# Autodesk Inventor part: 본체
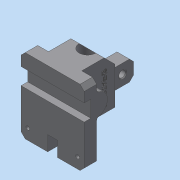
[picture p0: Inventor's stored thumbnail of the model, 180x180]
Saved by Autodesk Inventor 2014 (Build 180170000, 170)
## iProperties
Created: 2022-08
Part Number: 본체
Material: 일반
Document SubType Name: Modeling
Designer: dg
Density: 1 g/cm^3
Appearance: 기본값
Mass: 184.905 g
Surface Area: 337.564 cm^2
Volume: 184.905 cm^3
Author: dg
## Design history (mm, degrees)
sketch "스케치1"
  geometry: L1 (0, 0)-(27, 0); L2 (27, 0)-(45, -18); L3 (45, -18)-(45, -58); L4 (45, -58)-(4, -58); L5 (4, -58)-(4, -90); L6 (4, -90)-(0, -90); L7 (0, -90)-(0, 0)
  constraints: 14 end point, 4 parallel, 1 horizontal, 1 perpendicular
  dimensions: "d0" = 45 distance between parallel lines of L3 L7; "d1" = 18 horizontal distance of L1.end L2.end; "d2" = 45 deg angle of L2 L3; "d3" = 32 distance of L4.end L5.end; "d4" = 4 distance of L5.end L6.end; "d5" = 90 distance of L6.end L1.start
extrude "돌출1" new body sketch "스케치1" stored distance "d6" = 40; taper "d7" = 0 deg
sketch "스케치2"
  geometry: L1 (0, -90)-(0, 0) reference; L2 (0, 0)-(-15, 0); L3 (-15, 0)-(-15, -17); L4 (-15, -17)-(-7, -17); L5 (-7, -17)-(-7, -37); L6 (-7, -37)-(-15, -37); L7 (-15, -37)-(-15, -90); L8 (-15, -90)-(0, -90); A1 r 13 centre (0, -27) between (0, -40) and (0, -14); 1 further point
  constraints: 14 end point, 4 parallel, 3 point on line, 2 perpendicular, 2 point on circle, 1 centre point, 1 collinear, 1 horizontal alignment, 1 midpoint
  dimensions: "d8" = 13 radius of A1; "d9" = 20 distance of L4.end L5.end; "d10" = 27 distance from line of L2 A1.centre; "d11" = 8 distance of L3.end L4.end; "d12" = 8 distance of L5.end L6.end; "d13" = 15 distance of L1.end L2.end
extrude "돌출2" join sketch "스케치2" stored distance "d14" = 76; taper "d15" = 0 deg
sketch "스케치3"
  geometry: L1 (58, -60)-(-18, -60) reference; 3 further points
  constraints: 1 midpoint, 1 vertical alignment
  dimensions: "d16" = 42 distance from line of L1 point (20, -18)
hole "구멍1" sketch "스케치3" at (20, -18) diameter "d17" = 20; stored, may be unused: countersink angle "d21" = 90 deg, drill point angle "d23" = 118 deg; dims "d18" = 6, "d19" = 29, "d20" = 7, "d22" = 8
sketch "스케치4"
  geometry: L1 (0, 0)-(40, 0) reference; C1 r 10 at (20, 23) reference; A1 r 29 centre (20, 23) between (2.336, 0) and (37.664, 0); 1 further point
  constraints: 2 point on circle, 2 point on line, 1 centre point, 1 coincident
  dimensions: "d24" = 58 diameter of A1
extrude "돌출3" cut sketch "스케치4" distance "d25" = 18; taper "d26" = 0 deg
sketch "스케치5"
  geometry: L1 (76, 0)-(0, 0) reference; L2 (55.664, 19)-(58, 19) reference; L3 (32, 13.627)-(32, 0); L4 (44, 13.627)-(44, 0); A1 r 29 centre (38, 42) between (20.336, 19) and (55.664, 19) reference; 1 further point
  constraints: 4 end point, 2 perpendicular, 2 point on circle, 2 point on line, 1 horizontal alignment
  dimensions: "d27" = 12 distance between parallel lines of L3 L4
extrude "돌출4" cut sketch "스케치5" distance "d28" = 18; taper "d29" = 0 deg
sketch "스케치6"
  geometry: L1 (0, 50)-(18, 50) reference; L2 (-58, 50)-(-40, 50) reference; L3 (10, 37)-(-50, 37); L4 (-10, -40)-(-30, -40) reference; 3 further points
  constraints: 2 end point, 2 midpoint, 1 vertical alignment
  dimensions: "d30" = 13 distance from line of L2 L3.end; "d31" = 13 distance from line of L1 L3.start; "d32" = 60 distance of L3.end L3.start
hole "구멍2" sketch "스케치6" at (10, 37), (-50, 37) diameter "d33" = 4.5; stored, may be unused: countersink angle "d37" = 90 deg, drill point angle "d39" = 118 deg; dims "d34" = 6, "d35" = 8, "d36" = 4.4, "d38" = 8
sketch "스케치7"
  geometry: L1 (45, -18)-(45, -58) reference; L2 (45, -29)-(75, -29); L3 (75, -29)-(75, -53); L4 (75, -53)-(45, -53); L5 (41.5, -58)-(12.5, -58) reference; L6 (-15, -90)-(-15, -37) reference; C1 r 4 at (62, -41); 2 further points
  constraints: 6 end point, 3 perpendicular, 2 point on line, 1 centre point, 1 horizontal alignment, 1 midpoint
  dimensions: "d40" = 5 distance from line of L1.end L4; "d41" = 24 distance of L2.end L3.end; "d42" = 30 distance of L2.start L2.end; "d43" = 8 diameter of C1; "d44" = 77 distance from line of L6 C1.centre
extrude "돌출5" join sketch "스케치7" stored distance "d45" = 15; taper "d46" = 0 deg
chamfer "모따기1" distance "d47" = 5; stored, may be unused: second distance "d48" = 2, angle "d49" = 45 deg
chamfer "모따기2" distance "d50" = 5; stored, may be unused: second distance "d51" = 2, angle "d52" = 45 deg
chamfer "모따기3" distance "d53" = 1; stored, may be unused: second distance "d54" = 2, angle "d55" = 45 deg
fillet "모깎기1" dims "d56" = 3
fillet "모깎기2" dims "d57" = 3
fillet "모깎기3" dims "d58" = 3
fillet "모깎기4" dims "d59" = 3
chamfer "모따기4" distance "d60" = 5; stored, may be unused: second distance "d61" = 2, angle "d62" = 45 deg
sketch "스케치8"
  geometry: L1 (58, 7)-(58, 40) reference; L2 (58, 45)-(18, 45) reference; 1 further point
  constraints: 1 other
  dimensions: "d63" = 26 distance from line of L1 point (32, 27); "d64" = 18 distance from line of L2 point (32, 27)
feature "엠보싱1" sketch "스케치8" dims "d0" = 45, "d1" = 18, "d2" = 45 deg, "d3" = 32, "d4" = 4, "d5" = 90, "d65" = 0.5, "d66" = 0
node "솔리드1"
